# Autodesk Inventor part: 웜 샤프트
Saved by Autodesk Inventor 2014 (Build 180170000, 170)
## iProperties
Created: 2026-07
Part Number: 웜 샤프트
Material: 일반
Document SubType Name: Modeling
Designer: dg
Density: 1 g/cm^3
Appearance: 기본값
Author: dg
Author: jhkim
Creation Date: 2026-07-02
Sending System: Autodesk Inventor 2027
Preprocessor: ST-DEVELOPER v20.1
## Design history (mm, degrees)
node "웜 샤프트1"
node "솔리드1"
node "기준1"
